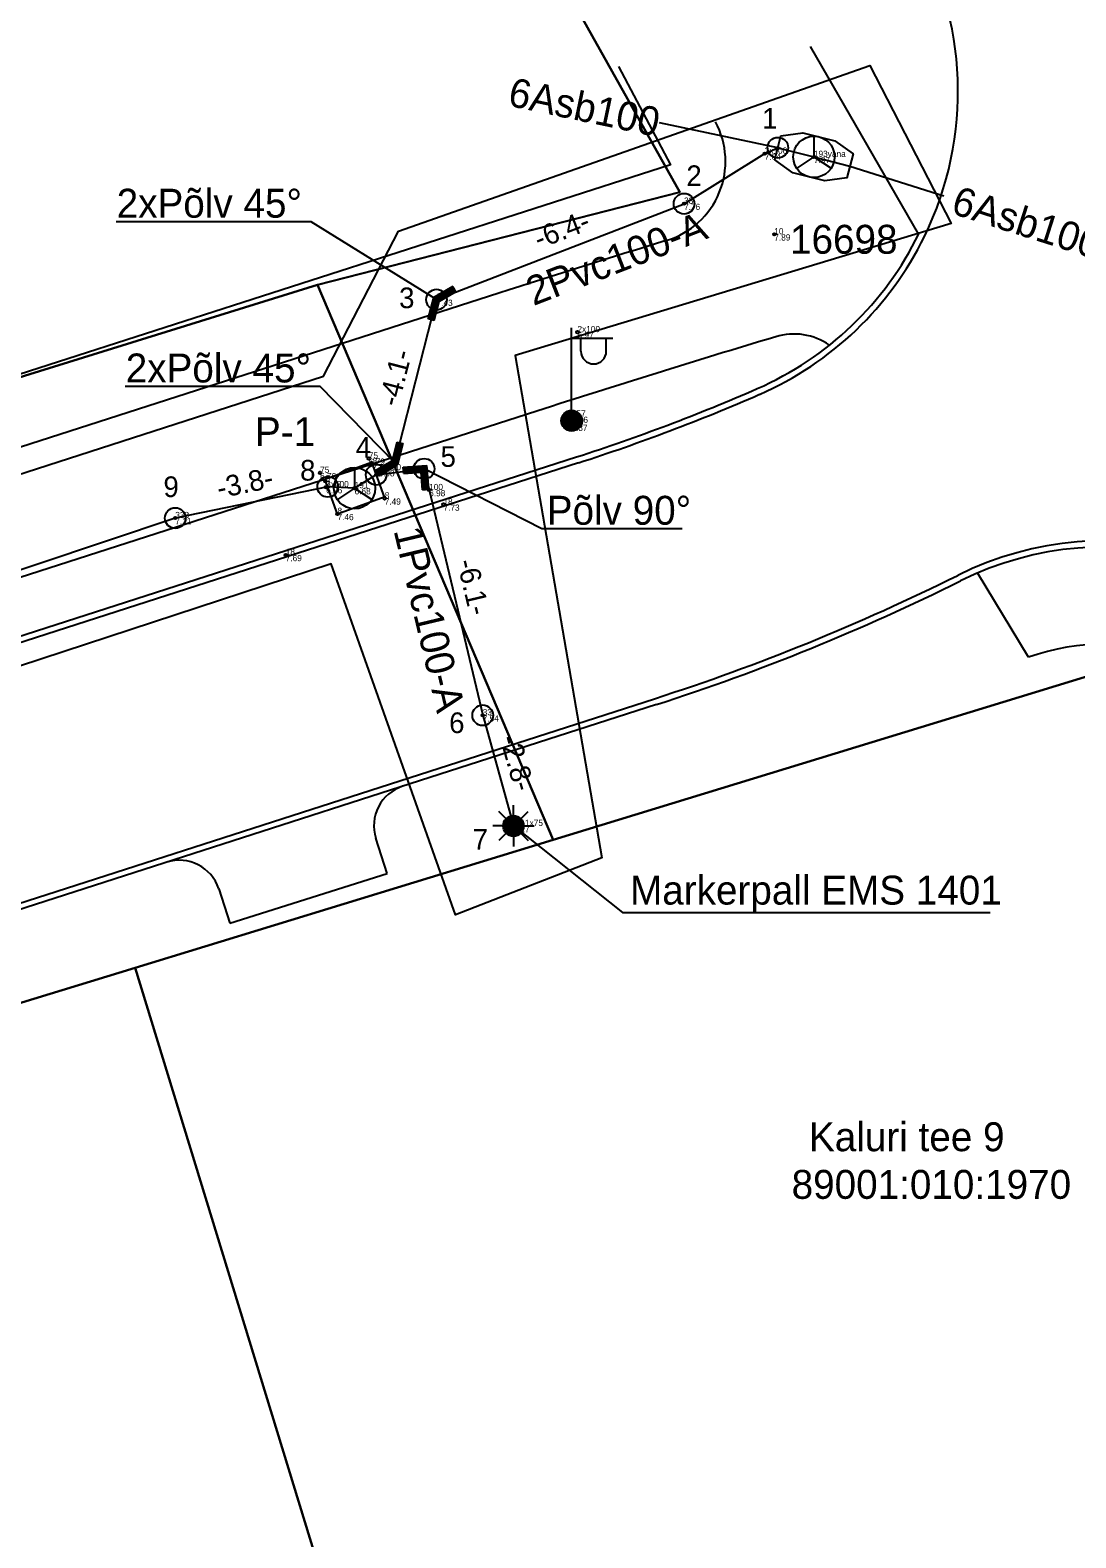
# Model space of a CAD drawing. Extents: x 546339 to 546593, y 6597108 to 6597251.
# Drawn here: x 546503.11 to 546528.43, y 6597175.02 to 6597211.53 of the extents above; entities that cross this region are included whole.
import ezdxf

# ---------------------------------------------------------------- set-up
doc = ezdxf.new("R2010")
doc.units = 0
for name, color, linetype in [('AED', 7, 'Continuous'), ('HOONE', 7, 'Continuous'), ('JOONSIDE', 7, 'Continuous'), ('KAEVUNR_SIKAEV', 7, 'Continuous'), ('KOORDPUNKT', 7, 'Continuous'), ('MOOTKORG-EH2000', 7, 'Continuous'), ('MOOTMPUNKT', 7, 'Continuous'), ('MOOTNR', 7, 'Continuous'), ('MOOTPIIR', 7, 'Continuous'), ('PIIR', 7, 'Continuous'), ('POST', 7, 'Continuous'), ('SIKAEV', 7, 'Continuous'), ('SITRASS', 7, 'Continuous'), ('TEE', 7, 'Continuous')]:
    doc.layers.add(name, color=color, linetype=linetype)

msp = doc.modelspace()

# ---------------------------------------------------------------- linework, layer by layer
at = {"layer": 'AED'}
msp.add_lwpolyline([(546517.355, 6597210.648), (546518.612, 6597208.263), (546491.076, 6597199.407)], dxfattribs=at)
at = {"layer": 'HOONE'}
msp.add_lwpolyline([(546516.221, 6597202.1), (546516.217, 6597202.041)], dxfattribs=at)
at = {"layer": 'KOORDPUNKT'}
for centre, radius in [((546521.213, 6597208.678), 0.25), ((546521.213, 6597208.678), 0.025), ((546521.213, 6597208.678), 0.0221), ((546521.213, 6597208.678), 0.0191), ((546521.213, 6597208.678), 0.0161), ((546521.213, 6597208.678), 0.0132), ((546521.213, 6597208.678), 0.0102), ((546521.213, 6597208.678), 0.00726), ((546521.213, 6597208.678), 0.0043), ((546518.941, 6597207.322), 0.25), ((546518.941, 6597207.322), 0.025), ((546518.941, 6597207.322), 0.0221), ((546518.941, 6597207.322), 0.0191), ((546518.941, 6597207.322), 0.0161), ((546518.941, 6597207.322), 0.0132), ((546518.941, 6597207.322), 0.0102), ((546518.941, 6597207.322), 0.00726), ((546518.941, 6597207.322), 0.0043), ((546512.949, 6597205.001), 0.25), ((546512.949, 6597205.001), 0.025), ((546512.949, 6597205.001), 0.0221), ((546512.949, 6597205.001), 0.0191), ((546512.949, 6597205.001), 0.0161), ((546512.949, 6597205.001), 0.0132), ((546512.949, 6597205.001), 0.0102), ((546512.949, 6597205.001), 0.00726), ((546512.949, 6597205.001), 0.0043), ((546512.648, 6597200.905), 0.25), ((546510.315, 6597200.469), 0.25), ((546511.486, 6597200.762), 0.25), ((546511.486, 6597200.762), 0.025), ((546511.486, 6597200.762), 0.0221), ((546511.486, 6597200.762), 0.0191), ((546511.486, 6597200.762), 0.0161), ((546511.486, 6597200.762), 0.0132), ((546511.486, 6597200.762), 0.0102), ((546511.486, 6597200.762), 0.00726), ((546511.486, 6597200.762), 0.0043), ((546512.648, 6597200.905), 0.025), ((546512.648, 6597200.905), 0.0221), ((546512.648, 6597200.905), 0.0191), ((546512.648, 6597200.905), 0.0161), ((546512.648, 6597200.905), 0.0132), ((546512.648, 6597200.905), 0.0102), ((546512.648, 6597200.905), 0.00726), ((546512.648, 6597200.905), 0.0043), ((546510.315, 6597200.469), 0.025), ((546510.315, 6597200.469), 0.0221), ((546510.315, 6597200.469), 0.0191), ((546510.315, 6597200.469), 0.0161), ((546510.315, 6597200.469), 0.0132), ((546510.315, 6597200.469), 0.0102), ((546510.315, 6597200.469), 0.00726), ((546510.315, 6597200.469), 0.0043), ((546506.623, 6597199.712), 0.25), ((546506.623, 6597199.712), 0.025), ((546506.623, 6597199.712), 0.0221), ((546506.623, 6597199.712), 0.0191), ((546506.623, 6597199.712), 0.0161), ((546506.623, 6597199.712), 0.0132), ((546506.623, 6597199.712), 0.0102), ((546506.623, 6597199.712), 0.00726), ((546506.623, 6597199.712), 0.0043), ((546514.066, 6597194.937), 0.25), ((546514.066, 6597194.937), 0.025), ((546514.066, 6597194.937), 0.0221), ((546514.066, 6597194.937), 0.0191), ((546514.066, 6597194.937), 0.0161), ((546514.066, 6597194.937), 0.0132), ((546514.066, 6597194.937), 0.0102), ((546514.066, 6597194.937), 0.00726), ((546514.066, 6597194.937), 0.0043), ((546514.811, 6597192.258), 0.25), ((546514.811, 6597192.258), 0.025), ((546514.811, 6597192.258), 0.0221), ((546514.811, 6597192.258), 0.0191), ((546514.811, 6597192.258), 0.0161), ((546514.811, 6597192.258), 0.0132), ((546514.811, 6597192.258), 0.0102), ((546514.811, 6597192.258), 0.00726), ((546514.811, 6597192.258), 0.0043)]:
    msp.add_circle(centre, radius, dxfattribs=at)
at = {"layer": 'MOOTMPUNKT'}
for centre in [(546520.894, 6597208.536), (546522.086, 6597208.457), (546518.941, 6597207.322), (546521.126, 6597206.582), (546512.949, 6597205.001), (546516.361, 6597204.213), (546516.225, 6597202.168), (546516.213, 6597201.973), (546511.309, 6597201.155), (546510.129, 6597200.806), (546511.4, 6597201.017), (546511.543, 6597200.871), (546510.259, 6597200.602), (546510.277, 6597200.461), (546510.965, 6597200.436), (546512.77, 6597200.39), (546511.694, 6597200.188), (546513.117, 6597200.04), (546506.623, 6597199.712), (546510.551, 6597199.812), (546509.297, 6597198.819), (546514.066, 6597194.937), (546514.811, 6597192.258)]:
    msp.add_circle(centre, 0.03, dxfattribs=at)
at = {"layer": 'MOOTPIIR'}
msp.add_lwpolyline([(546483.506, 6597194.527), (546510.21, 6597203.146), (546512.028, 6597206.657), (546523.437, 6597210.669), (546525.412, 6597206.845), (546514.849, 6597203.648), (546516.949, 6597191.487), (546513.407, 6597190.108), (546510.398, 6597198.602), (546490.433, 6597192.051)], dxfattribs=at)
at = {"layer": 'PIIR'}
for points in [[(546483.698, 6597217.73), (546491.04, 6597199.45), (546510.07, 6597205.36), (546518.84, 6597207.6), (546508.483, 6597226.076)], [(546508.483, 6597226.076), (546518.84, 6597207.6), (546510.07, 6597205.36), (546515.77, 6597191.92), (546529.93, 6597196.26), (546542.493, 6597175.58)], [(546510.07, 6597205.36), (546491.04, 6597199.45), (546466.79, 6597191.98), (546431.99, 6597181.07), (546399.93, 6597171.7), (546399.49, 6597172.55), (546362.07, 6597160.42), (546350.54, 6597167.22), (546341.457, 6597167.537)], [(546505.65, 6597188.82), (546515.77, 6597191.92), (546510.07, 6597205.36)], [(546542.493, 6597175.58), (546529.93, 6597196.26), (546515.77, 6597191.92), (546505.65, 6597188.82), (546512.531, 6597166.376)], [(546339.379, 6597150.424), (546339.82, 6597150.4), (546343.3, 6597148.09), (546350.66, 6597143.2), (546387.61, 6597151.42), (546402.5, 6597155.95), (546434.27, 6597166.43), (546452.55, 6597172.32), (546467.66, 6597177.18), (546479.16, 6597180.72), (546505.65, 6597188.82)], [(546512.531, 6597166.376), (546505.65, 6597188.82), (546479.16, 6597180.72), (546486.042, 6597158.239)]]:
    msp.add_lwpolyline(points, dxfattribs=at)
at = {"layer": 'POST'}
for p, q in [((546516.219, 6597202.321), (546516.219, 6597204.321)), ((546516.219, 6597204.071), (546517.219, 6597204.071)), ((546516.446, 6597203.75), (546516.446, 6597204.071)), ((546517.058, 6597203.75), (546517.058, 6597204.071)), ((546516.219, 6597202.07), (546516.219, 6597202.07))]:
    msp.add_line(p, q, dxfattribs=at)
for radius in [0.25, 0.225, 0.2, 0.175, 0.15, 0.125, 0.1, 0.075, 0.05, 0.025]:
    msp.add_circle((546516.219, 6597202.07), radius, dxfattribs=at)
msp.add_arc((546516.752, 6597203.75), 0.306, 180, 0, dxfattribs=at)
at = {"layer": 'SIKAEV'}
for p, q in [((546522.086, 6597208.957), (546522.086, 6597208.457)), ((546522.086, 6597208.457), (546521.671, 6597208.182)), ((546522.086, 6597208.457), (546522.501, 6597208.182)), ((546510.965, 6597200.936), (546510.965, 6597200.436)), ((546510.965, 6597200.436), (546510.55, 6597200.161)), ((546510.965, 6597200.436), (546511.38, 6597200.161))]:
    msp.add_line(p, q, dxfattribs=at)
for points in [[(546521.14, 6597208.387), (546521.287, 6597208.968), (546521.821, 6597209.04), (546522.596, 6597208.844), (546523.032, 6597208.527), (546522.885, 6597207.946), (546522.351, 6597207.874), (546521.576, 6597208.07)], [(546510.247, 6597200.654), (546511.375, 6597201.064), (546511.683, 6597200.218), (546510.555, 6597199.808)]]:
    msp.add_lwpolyline(points, close=True, dxfattribs=at)
for centre in [(546522.086, 6597208.457), (546510.965, 6597200.436)]:
    msp.add_circle(centre, 0.5, dxfattribs=at)
at = {"layer": 'SITRASS'}
for p, q in [((546513.345, 6597205.315), (546512.885, 6597205.05)), ((546513.382, 6597205.25), (546512.949, 6597205.001)), ((546513.024, 6597204.958), (546512.957, 6597205.092)), ((546513.046, 6597204.97), (546512.979, 6597205.105)), ((546513.068, 6597204.983), (546513, 6597205.117)), ((546513.42, 6597205.186), (546513.013, 6597204.952)), ((546513.089, 6597204.995), (546513.022, 6597205.13)), ((546513.111, 6597205.008), (546513.044, 6597205.142)), ((546513.133, 6597205.02), (546513.065, 6597205.155)), ((546513.154, 6597205.033), (546513.087, 6597205.167)), ((546513.176, 6597205.045), (546513.109, 6597205.18)), ((546513.198, 6597205.058), (546513.131, 6597205.192)), ((546513.219, 6597205.07), (546513.152, 6597205.205)), ((546513.241, 6597205.083), (546513.174, 6597205.217)), ((546513.263, 6597205.095), (546513.196, 6597205.23)), ((546513.285, 6597205.108), (546513.217, 6597205.242)), ((546513.306, 6597205.12), (546513.239, 6597205.255)), ((546513.328, 6597205.133), (546513.261, 6597205.267)), ((546513.35, 6597205.145), (546513.283, 6597205.28)), ((546513.371, 6597205.158), (546513.304, 6597205.292)), ((546513.393, 6597205.17), (546513.326, 6597205.305)), ((546513.42, 6597205.186), (546513.345, 6597205.315)), ((546513.415, 6597205.183), (546513.372, 6597205.269)), ((546512.747, 6597204.538), (546512.885, 6597205.05)), ((546512.901, 6597204.533), (546512.8, 6597204.735)), ((546512.911, 6597204.57), (546512.81, 6597204.772)), ((546512.819, 6597204.518), (546512.949, 6597205.001)), ((546512.92, 6597204.606), (546512.819, 6597204.808)), ((546512.93, 6597204.642), (546512.829, 6597204.844)), ((546512.94, 6597204.679), (546512.839, 6597204.881)), ((546512.95, 6597204.715), (546512.849, 6597204.917)), ((546512.959, 6597204.751), (546512.859, 6597204.953)), ((546512.969, 6597204.788), (546512.868, 6597204.99)), ((546512.979, 6597204.824), (546512.878, 6597205.026)), ((546512.891, 6597204.499), (546513.013, 6597204.952)), ((546512.989, 6597204.86), (546512.892, 6597205.055)), ((546512.999, 6597204.897), (546512.914, 6597205.067)), ((546513.008, 6597204.933), (546512.935, 6597205.08)), ((546512.891, 6597204.499), (546512.747, 6597204.538)), ((546512.761, 6597204.534), (546512.751, 6597204.554)), ((546512.793, 6597204.525), (546512.761, 6597204.59)), ((546512.825, 6597204.517), (546512.77, 6597204.626)), ((546512.858, 6597204.508), (546512.78, 6597204.663)), ((546512.89, 6597204.499), (546512.79, 6597204.699)), ((546511.988, 6597201.554), (546511.872, 6597201.1)), ((546512.061, 6597201.536), (546511.937, 6597201.051)), ((546511.96, 6597201.447), (546512.064, 6597201.246)), ((546511.97, 6597201.483), (546512.073, 6597201.282)), ((546511.979, 6597201.52), (546512.083, 6597201.319)), ((546511.988, 6597201.554), (546512.133, 6597201.517)), ((546511.99, 6597201.554), (546512.092, 6597201.355)), ((546512.133, 6597201.517), (546512.001, 6597201.003)), ((546512.022, 6597201.546), (546512.101, 6597201.392)), ((546512.054, 6597201.537), (546512.111, 6597201.428)), ((546512.087, 6597201.529), (546512.12, 6597201.465)), ((546512.119, 6597201.521), (546512.129, 6597201.501)), ((546511.468, 6597200.861), (546511.872, 6597201.1)), ((546511.839, 6597201.081), (546511.908, 6597200.947)), ((546511.861, 6597201.094), (546511.93, 6597200.96)), ((546511.876, 6597201.119), (546511.951, 6597200.973)), ((546511.886, 6597201.155), (546511.973, 6597200.986)), ((546511.895, 6597201.192), (546511.994, 6597200.998)), ((546511.904, 6597201.228), (546512.008, 6597201.027)), ((546511.914, 6597201.264), (546512.017, 6597201.064)), ((546511.923, 6597201.301), (546512.026, 6597201.1)), ((546511.932, 6597201.337), (546512.036, 6597201.137)), ((546511.942, 6597201.374), (546512.045, 6597201.173)), ((546511.951, 6597201.41), (546512.054, 6597201.209)), ((546511.468, 6597200.861), (546511.544, 6597200.732)), ((546511.473, 6597200.864), (546511.517, 6597200.778)), ((546511.495, 6597200.877), (546511.563, 6597200.743)), ((546511.506, 6597200.797), (546511.937, 6597201.051)), ((546511.516, 6597200.89), (546511.585, 6597200.756)), ((546511.538, 6597200.902), (546511.606, 6597200.769)), ((546511.544, 6597200.732), (546512.001, 6597201.003)), ((546511.559, 6597200.915), (546511.628, 6597200.782)), ((546511.581, 6597200.928), (546511.649, 6597200.794)), ((546511.602, 6597200.941), (546511.671, 6597200.807)), ((546511.624, 6597200.954), (546511.693, 6597200.82)), ((546511.645, 6597200.966), (546511.714, 6597200.833)), ((546511.667, 6597200.979), (546511.736, 6597200.845)), ((546511.689, 6597200.992), (546511.757, 6597200.858)), ((546511.71, 6597201.005), (546511.779, 6597200.871)), ((546511.732, 6597201.017), (546511.8, 6597200.884)), ((546511.753, 6597201.03), (546511.822, 6597200.896)), ((546511.775, 6597201.043), (546511.843, 6597200.909)), ((546511.796, 6597201.056), (546511.865, 6597200.922)), ((546511.818, 6597201.068), (546511.887, 6597200.935)), ((546512.143, 6597200.941), (546512.717, 6597200.985)), ((546512.155, 6597200.791), (546512.143, 6597200.941)), ((546512.145, 6597200.915), (546512.179, 6597200.943)), ((546512.148, 6597200.884), (546512.221, 6597200.947)), ((546512.149, 6597200.866), (546512.648, 6597200.905)), ((546512.15, 6597200.853), (546512.263, 6597200.95)), ((546512.153, 6597200.822), (546512.305, 6597200.953)), ((546512.155, 6597200.791), (546512.347, 6597200.956)), ((546512.155, 6597200.791), (546512.579, 6597200.824)), ((546512.197, 6597200.794), (546512.389, 6597200.96)), ((546512.239, 6597200.798), (546512.431, 6597200.963)), ((546512.281, 6597200.801), (546512.473, 6597200.966)), ((546512.324, 6597200.804), (546512.515, 6597200.969)), ((546512.366, 6597200.807), (546512.557, 6597200.973)), ((546512.408, 6597200.811), (546512.599, 6597200.976)), ((546512.45, 6597200.814), (546512.641, 6597200.979)), ((546512.492, 6597200.817), (546512.683, 6597200.983)), ((546512.534, 6597200.82), (546512.717, 6597200.979)), ((546512.576, 6597200.824), (546512.72, 6597200.948)), ((546512.612, 6597200.4), (546512.579, 6597200.824)), ((546512.581, 6597200.795), (546512.722, 6597200.917)), ((546512.583, 6597200.764), (546512.724, 6597200.886)), ((546512.586, 6597200.733), (546512.727, 6597200.855)), ((546512.588, 6597200.702), (546512.729, 6597200.824)), ((546512.591, 6597200.671), (546512.732, 6597200.793)), ((546512.593, 6597200.64), (546512.734, 6597200.762)), ((546512.595, 6597200.609), (546512.736, 6597200.731)), ((546512.687, 6597200.406), (546512.648, 6597200.905)), ((546512.761, 6597200.412), (546512.717, 6597200.985)), ((546512.598, 6597200.579), (546512.739, 6597200.7)), ((546512.6, 6597200.548), (546512.741, 6597200.669)), ((546512.603, 6597200.517), (546512.744, 6597200.638)), ((546512.605, 6597200.486), (546512.746, 6597200.607)), ((546512.607, 6597200.455), (546512.748, 6597200.576)), ((546512.61, 6597200.424), (546512.751, 6597200.545)), ((546512.612, 6597200.4), (546512.761, 6597200.412)), ((546512.622, 6597200.401), (546512.753, 6597200.515)), ((546512.664, 6597200.404), (546512.756, 6597200.484)), ((546512.706, 6597200.408), (546512.758, 6597200.453)), ((546512.748, 6597200.411), (546512.761, 6597200.422)), ((546514.811, 6597192.508), (546514.811, 6597192.758)), ((546514.634, 6597192.435), (546514.457, 6597192.612)), ((546514.988, 6597192.435), (546515.165, 6597192.612)), ((546514.561, 6597192.258), (546514.311, 6597192.258)), ((546514.634, 6597192.081), (546514.457, 6597191.904)), ((546514.811, 6597192.008), (546514.811, 6597191.758)), ((546514.988, 6597192.081), (546515.165, 6597191.904)), ((546515.061, 6597192.258), (546515.311, 6597192.258))]:
    msp.add_line(p, q, dxfattribs=at)
for points in [[(546521.213, 6597208.678), (546518.351, 6597209.28)], [(546511.486, 6597200.762), (546511.937, 6597201.051), (546512.949, 6597205.001), (546518.941, 6597207.322), (546520.894, 6597208.536), (546521.213, 6597208.678)], [(546521.213, 6597208.678), (546522.086, 6597208.457)], [(546522.086, 6597208.457), (546522.959, 6597208.236), (546525.234, 6597207.51)], [(546512.949, 6597205.001), (546509.914, 6597206.887), (546505.189, 6597206.887)], [(546511.937, 6597201.051), (546510.133, 6597202.898), (546505.407, 6597202.898)], [(546511.486, 6597200.762), (546510.965, 6597200.436)], [(546511.486, 6597200.762), (546512.648, 6597200.905), (546514.066, 6597194.937), (546514.811, 6597192.258)], [(546518.897, 6597199.453), (546515.495, 6597199.453), (546512.648, 6597200.905)], [(546510.965, 6597200.436), (546510.315, 6597200.469), (546506.623, 6597199.712), (546498.254, 6597196.907), (546489.712, 6597194.378), (546487.403, 6597193.544)], [(546514.811, 6597192.258), (546517.454, 6597190.162), (546526.351, 6597190.162)]]:
    msp.add_lwpolyline(points, dxfattribs=at)
for radius in [0.25, 0.225, 0.2, 0.175, 0.15, 0.125, 0.1, 0.075, 0.05, 0.025]:
    msp.add_circle((546514.811, 6597192.258), radius, dxfattribs=at)
at = {"layer": 'TEE'}
for p, q in [((546520.712, 6597202.846), (546520.712, 6597202.846)), ((546486.271, 6597191.511), (546516.341, 6597201.194)), ((546516.341, 6597201.194), (546516.341, 6597201.194)), ((546516.387, 6597201.051), (546486.317, 6597191.368)), ((546525.567, 6597198.326), (546525.567, 6597198.326)), ((546527.279, 6597196.342), (546526.05, 6597198.384)), ((546518.272, 6597195.197), (546396.577, 6597156.011)), ((546511.757, 6597191.106), (546511.482, 6597191.96)), ((546507.942, 6597189.903), (546511.757, 6597191.106)), ((546507.674, 6597190.734), (546507.942, 6597189.903))]:
    msp.add_line(p, q, dxfattribs=at)
for points in [[(546521.992, 6597211.128), (546524.618, 6597206.577)], [(546514.456, 6597205.157), (546396.804, 6597167.285), (546396.804, 6597167.285)], [(546515.375, 6597202.301), (546397.724, 6597164.429), (546397.724, 6597164.429)], [(546396.531, 6597156.154), (546518.226, 6597195.34), (546518.226, 6597195.34)]]:
    msp.add_lwpolyline(points, dxfattribs=at)
for centre, radius, start, end in [((546517.573, 6597210.041), 8, 333.9816, 30.3231), ((546517.944, 6597208.35), 2, 287.0528, 28.5139), ((546517.573, 6597210.041), 7.85, 293.5658, 333.9816), ((546608.706, 6596912.457), 307.5, 107.05276, 107.8487), ((546517.573, 6597210.041), 8, 293.5658, 333.9816), ((546608.706, 6596912.457), 304.5, 106.7086, 107.8487), ((546521.606, 6597202.687), 1.482, 54.8003, 107.4762), ((546501.981, 6597245.789), 46.85, 287.8487, 293.5658), ((546501.981, 6597245.789), 47, 287.8487, 293.5658), ((546529.128, 6597191.162), 8, 31.2085, 116.4253), ((546529.128, 6597191.162), 7.85, 31.2085, 116.4253), ((546501.994, 6597245.755), 52.964, 287.8458, 296.4282), ((546501.994, 6597245.755), 53.114, 287.8458, 296.4282), ((546529.128, 6597191.162), 5.5, 31.2085, 109.6372), ((546512.434, 6597192.267), 1, 107.8487, 197.8487), ((546506.723, 6597190.428), 1, 17.8487, 107.8487)]:
    msp.add_arc(centre, radius, start, end, dxfattribs=at)

# ---------------------------------------------------------------- texts
at = {"layer": 'JOONSIDE'}
for s, rotation, p in [('-6.4-', 21.1717, (546515.427, 6597206.218)), ('-4.1-', 75.6219, (546512.021, 6597202.386)), ('-3.8-', 11.5841, (546507.684, 6597200.185)), ('-6.1-', 283.3693, (546513.438, 6597198.66)), ('-2.8-', 285.5407, (546514.478, 6597194.387))]:
    msp.add_text(s, height=0.5, rotation=rotation, dxfattribs=at).set_placement(p)
at = {"layer": 'KAEVUNR_SIKAEV'}
for s, p in [('16698', (546521.507, 6597206.112)), ('P-1', (546508.552, 6597201.454))]:
    msp.add_text(s, height=0.7, dxfattribs=at).set_placement(p)
at = {"layer": 'KOORDPUNKT'}
for s, p in [('1', (546520.832, 6597209.139)), ('2', (546518.997, 6597207.751)), ('3', (546512.042, 6597204.794)), ('4', (546510.993, 6597201.176)), ('5', (546513.046, 6597200.952)), ('8', (546509.646, 6597200.62)), ('9', (546506.337, 6597200.221)), ('6', (546513.254, 6597194.507)), ('7', (546513.824, 6597191.685))]:
    msp.add_text(s, height=0.5, dxfattribs=at).set_placement(p)
at = {"layer": 'MOOTKORG-EH2000'}
for s, p in [('7.04', (546520.894, 6597208.386)), ('7.97', (546522.086, 6597208.307)), ('7.76', (546518.941, 6597207.172)), ('7.89', (546521.126, 6597206.432)), ('7.43', (546512.949, 6597204.851)), ('6.97', (546516.361, 6597204.063)), ('7.86', (546516.225, 6597202.018)), ('7.87', (546516.213, 6597201.823)), ('6.79', (546511.309, 6597201.005)), ('6.76', (546510.129, 6597200.656)), ('7.51', (546511.4, 6597200.867)), ('6.98', (546511.543, 6597200.721)), ('7.47', (546510.259, 6597200.452)), ('6.96', (546510.277, 6597200.311)), ('6.68', (546510.965, 6597200.286)), ('6.98', (546512.77, 6597200.24)), ('7.49', (546511.694, 6597200.038)), ('7.73', (546513.117, 6597199.89)), ('7.11', (546506.623, 6597199.562)), ('7.46', (546510.551, 6597199.662)), ('7.69', (546509.297, 6597198.669)), ('7.54', (546514.066, 6597194.787)), ('7.27', (546514.811, 6597192.108))]:
    msp.add_text(s, height=0.15, dxfattribs=at).set_placement(p)
at = {"layer": 'MOOTNR'}
for s, p in [('2x100', (546520.894, 6597208.536)), ('193vana', (546522.086, 6597208.457)), ('33', (546518.941, 6597207.322)), ('10', (546521.126, 6597206.582)), ('33', (546512.949, 6597205.001)), ('2x100', (546516.361, 6597204.213)), ('157', (546516.225, 6597202.168)), ('157', (546516.213, 6597201.973)), ('75', (546511.309, 6597201.155)), ('8', (546511.4, 6597201.017)), ('75', (546510.129, 6597200.806)), ('8', (546510.259, 6597200.602)), ('3x100', (546511.543, 6597200.871)), ('3x100', (546510.277, 6597200.461)), ('191', (546510.965, 6597200.436)), ('100', (546512.77, 6597200.39)), ('8', (546511.694, 6597200.188)), ('18', (546513.117, 6597200.04)), ('333', (546506.623, 6597199.712)), ('8', (546510.551, 6597199.812)), ('18', (546509.297, 6597198.819)), ('33', (546514.066, 6597194.937)), ('22 1x75', (546514.811, 6597192.258))]:
    msp.add_text(s, height=0.15, dxfattribs=at).set_placement(p)
at = {"layer": 'PIIR'}
for s, p in [('Kaluri tee 9', (546521.966, 6597184.384)), ('89001:010:1970', (546521.546, 6597183.231))]:
    msp.add_text(s, height=0.7, dxfattribs=at).set_placement(p)
at = {"layer": 'SITRASS'}
for s, rotation, p in [('6Asb100 ', 348.121, (546514.649, 6597209.701)), (' 6Asb100+6Pvc100 ', 342.3016, (546525.128, 6597207.177)), ('2Pvc100-A', 21.1717, (546515.293, 6597204.844)), ('1Pvc100-A', 283.3693, (546511.906, 6597199.413))]:
    msp.add_text(s, height=0.7, rotation=rotation, dxfattribs=at).set_placement(p)
for s, p in [('2xPõlv 45°', (546505.205, 6597206.985)), ('2xPõlv 45°', (546505.424, 6597202.996)), ('Põlv 90°', (546515.617, 6597199.551)), ('Markerpall EMS 1401', (546517.634, 6597190.355))]:
    msp.add_text(s, height=0.7, dxfattribs=at).set_placement(p)

doc.saveas('drawing.dxf')
